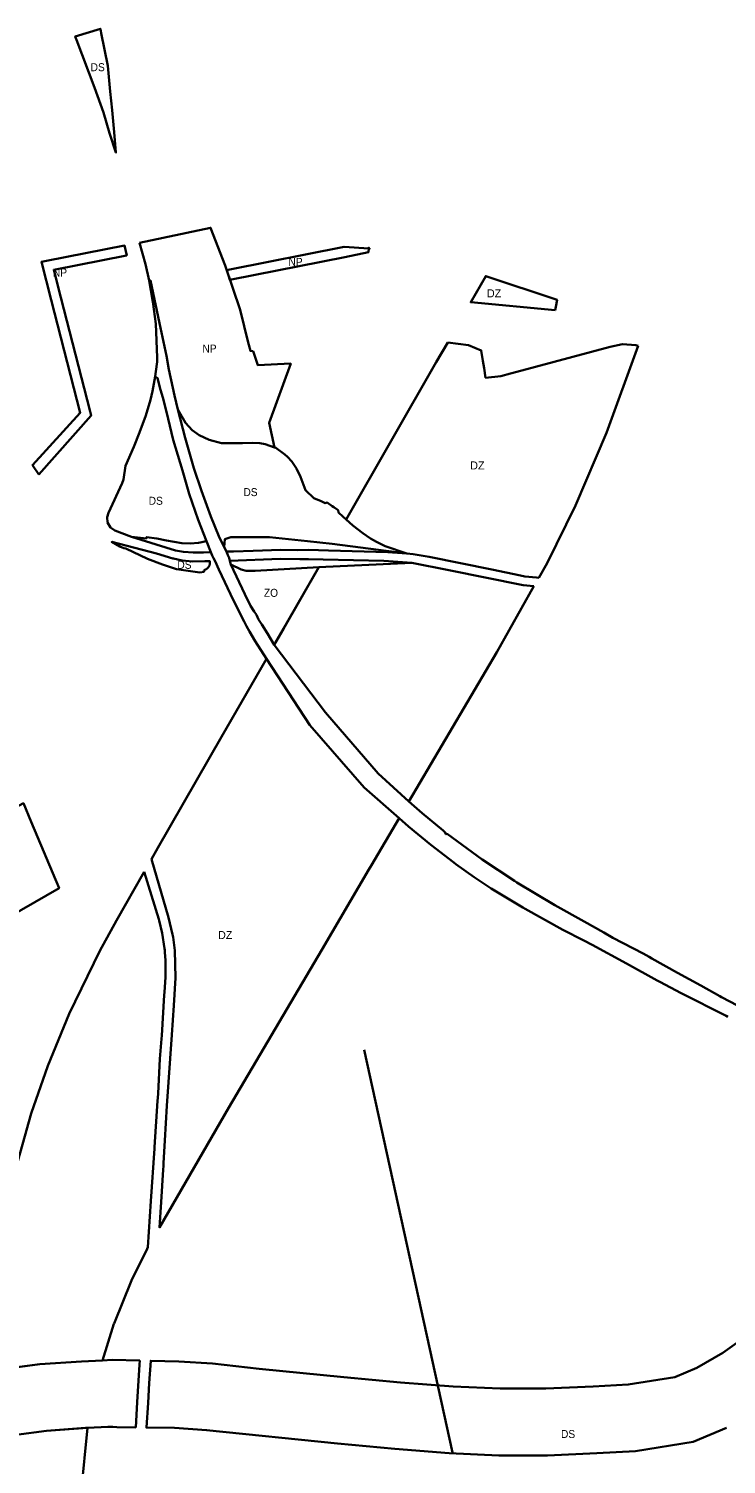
# Model space of a CAD drawing. Extents: x -650276 to -642489, y -1074311 to -1066658.
# Drawn here: x -647975 to -646929, y -1069108 to -1066956 of the extents above; entities that cross this region are included whole.
import ezdxf

# ---------------------------------------------------------------- set-up
doc = ezdxf.new("R2010")
doc.units = 0
doc.header["$LTSCALE"] = 4.8
doc.header["$PDMODE"] = 32
doc.header["$PDSIZE"] = 2.4
for name, color, linetype, lineweight in [('24', 7, 'Continuous', 35), ('25', 7, 'Continuous', 35), ('42', 7, 'Continuous', 35), ('48', 7, 'Continuous', 35), ('54', 7, 'Continuous', 35)]:
    doc.layers.add(name, color=color, linetype=linetype, lineweight=lineweight)
doc.layers.add('62', color=7, linetype='Continuous')
doc.layers.add('63', color=7, linetype='Continuous')

msp = doc.modelspace()

# ---------------------------------------------------------------- linework, layer by layer
at = {"layer": '24'}
for points in [[(-647876.57, -1067043.5), (-647863.04, -1067081.36), (-647853.65, -1067111.91), (-647844.3, -1067141.25), (-647847.09, -1067110.58), (-647850.07, -1067077.71), (-647852.63, -1067049.52), (-647856.11, -1067011.21), (-647866.14, -1066961.98), (-647867.46, -1066955.52), (-647905.28, -1066967.07), (-647903.5, -1066972.05)], [(-647754.88, -1067737.59), (-647743.12, -1067739.93), (-647728.29, -1067740.64), (-647713.15, -1067741), (-647702.21, -1067740.43), (-647708.71, -1067723.99), (-647720.45, -1067726.49), (-647732.71, -1067727.02), (-647745.41, -1067726.6), (-647768.53, -1067722.82), (-647783.13, -1067719.68), (-647798.17, -1067717.58), (-647798.5, -1067719.67), (-647821.02, -1067717.33)], [(-647596.91, -1067736.61), (-647572.33, -1067737.03), (-647555.58, -1067736.71), (-647525.685, -1067737.542), (-647436.72, -1067740.02), (-647408.2, -1067742.37), (-647520.145, -1067727.879), (-647557, -1067724), (-647614, -1067718), (-647643, -1067718), (-647672, -1067718), (-647680.804, -1067720.745), (-647681.91, -1067732.74), (-647678.66, -1067739.38), (-647678.66, -1067739.38), (-647667.76, -1067739.01), (-647638.75, -1067738.03)], [(-647540.208, -1067762.876), (-647400.63, -1067756.19), (-647442.6, -1067753.13), (-647533.597, -1067751.344), (-647555.67, -1067750.91), (-647568.36, -1067750.7), (-647597.83, -1067750.21), (-647673.47, -1067753.48), (-647672.05, -1067758.98), (-647672.05, -1067758.98), (-647656.469, -1067766.309), (-647649.22, -1067768.38), (-647635.758, -1067768.38)], [(-647540.208, -1067762.876), (-647400.63, -1067756.19), (-647442.6, -1067753.13), (-647533.597, -1067751.344), (-647555.67, -1067750.91), (-647568.36, -1067750.7), (-647597.83, -1067750.21), (-647673.47, -1067753.48), (-647672.05, -1067758.98), (-647672.05, -1067758.98), (-647656.469, -1067766.309), (-647649.22, -1067768.38), (-647635.758, -1067768.38)]]:
    msp.add_lwpolyline(points, close=True, dxfattribs=at)
for points in [[(-647606.818, -1067879.061), (-647617.25, -1067861.95), (-647625.37, -1067848.86), (-647630.3, -1067841.02), (-647633.69, -1067834.31), (-647637.21, -1067829.29), (-647642.29, -1067820.76), (-647650.8, -1067803.28), (-647672.05, -1067758.98), (-647673.47, -1067753.48), (-647673.47, -1067753.48), (-647674.67, -1067748.73), (-647676.47, -1067744.5), (-647678.66, -1067739.38), (-647681.91, -1067732.74), (-647690.09, -1067716.05), (-647702.04, -1067686.86), (-647715.92, -1067648.12), (-647727.37, -1067614.33), (-647740.49, -1067568.67), (-647751.41, -1067526.58), (-647756.55, -1067505.32), (-647759.16, -1067494.01), (-647764.89, -1067466.64), (-647768.5, -1067446.04), (-647778.78, -1067397.1), (-647792.52, -1067332.74), (-647794.54, -1067333.14), (-647788.77, -1067365.03), (-647784.55, -1067398.01), (-647782.39, -1067448.34), (-647782.5, -1067455.11), (-647784.36, -1067469.6), (-647785.64, -1067477.02), (-647781.85, -1067479.19), (-647777.55, -1067496.95), (-647773.96, -1067508.48), (-647768.5, -1067529.75), (-647758.25, -1067571.79), (-647744.61, -1067617.96), (-647734.63, -1067652.57), (-647721.05, -1067691.73), (-647708.71, -1067723.99), (-647702.21, -1067740.43), (-647699.89, -1067745.24), (-647697.85, -1067749.46), (-647695.71, -1067753.9), (-647690.19, -1067766.37), (-647668.13, -1067812.76), (-647651.94, -1067844.36), (-647648.33, -1067851.17), (-647643.83, -1067859.13), (-647635.77, -1067873.43), (-647618.773, -1067899.914)], [(-647708.71, -1067723.99), (-647721.05, -1067691.73), (-647734.63, -1067652.57), (-647744.61, -1067617.96), (-647758.25, -1067571.79), (-647768.5, -1067529.75), (-647773.96, -1067508.48), (-647777.55, -1067496.95), (-647781.85, -1067479.19), (-647785.64, -1067477.02), (-647789.39, -1067498.84), (-647792.54, -1067511.85), (-647799.39, -1067535.48)], [(-647799.39, -1067535.48), (-647808.71, -1067561.03), (-647817.59, -1067582.4)], [(-647654.743, -1067576.996), (-647685.968, -1067576.68), (-647704.458, -1067572.034), (-647719.661, -1067564.884), (-647729.802, -1067557.462), (-647740.124, -1067546.265), (-647751.41, -1067526.58)], [(-647751.41, -1067526.58), (-647740.49, -1067568.67), (-647727.37, -1067614.33), (-647715.92, -1067648.12), (-647702.04, -1067686.86)], [(-647817.59, -1067582.4), (-647829.97, -1067610.62), (-647832.8, -1067631.53), (-647835.06, -1067637.01), (-647855.24, -1067681.26), (-647857.51, -1067687.74), (-647856.9, -1067695.97)], [(-647606.559, -1067583.309), (-647620.586, -1067578.478), (-647628.441, -1067576.759), (-647640.087, -1067576.306), (-647654.743, -1067576.996)], [(-647547.663, -1067659.519), (-647560.187, -1067647.458), (-647567.744, -1067627.24), (-647573.605, -1067614.951), (-647580.539, -1067604.432), (-647586.864, -1067597.411), (-647591.227, -1067593.613), (-647604.415, -1067584.047), (-647606.559, -1067583.309)], [(-647499.095, -1067691.163), (-647503.97, -1067686.73), (-647510.6, -1067680.86), (-647511.24, -1067677.53), (-647517.74, -1067672.85), (-647520.13, -1067671.13), (-647527.76, -1067665.65), (-647530.82, -1067666.65), (-647536.83, -1067663.64), (-647547.663, -1067659.519)], [(-647702.04, -1067686.86), (-647690.09, -1067716.05), (-647681.91, -1067732.74)], [(-647462.45, -1067719.84), (-647474.13, -1067711.81), (-647489.3, -1067700.07), (-647499.095, -1067691.163)], [(-647856.9, -1067695.97), (-647852.3, -1067703.36), (-647845.74, -1067707.59), (-647821.02, -1067717.33)], [(-647783.54, -1067742.11), (-647850.45, -1067724.77), (-647838.18, -1067731.62), (-647832.56, -1067734.22), (-647829.49, -1067734.58), (-647796.87, -1067750.25), (-647774.54, -1067758.68), (-647753.53, -1067765.58), (-647718.54, -1067770.6), (-647712.01, -1067769.63), (-647712.26, -1067767.28)], [(-647821.02, -1067717.33), (-647798.5, -1067719.67), (-647798.17, -1067717.58), (-647783.13, -1067719.68), (-647768.53, -1067722.82), (-647745.41, -1067726.6), (-647732.71, -1067727.02), (-647720.45, -1067726.49), (-647708.71, -1067723.99)], [(-647681.91, -1067732.74), (-647680.804, -1067720.745), (-647672, -1067718), (-647643, -1067718), (-647614, -1067718)], [(-647614, -1067718), (-647557, -1067724), (-647520.145, -1067727.879), (-647408.2, -1067742.37), (-647440.81, -1067731.38), (-647453.87, -1067724.97), (-647462.45, -1067719.84)], [(-647712.26, -1067767.28), (-647711.773, -1067767.135), (-647711.286, -1067766.968), (-647710.799, -1067766.777), (-647710.315, -1067766.562), (-647709.834, -1067766.324), (-647709.359, -1067766.062), (-647708.892, -1067765.776), (-647708.433, -1067765.466), (-647707.985, -1067765.133), (-647707.55, -1067764.777), (-647707.128, -1067764.398), (-647706.723, -1067763.999), (-647706.335, -1067763.579), (-647705.966, -1067763.14), (-647705.617, -1067762.683), (-647705.29, -1067762.21), (-647704.985, -1067761.721), (-647704.704, -1067761.22), (-647704.447, -1067760.707), (-647704.216, -1067760.184), (-647704.01, -1067759.653), (-647703.83, -1067759.117), (-647703.675, -1067758.576), (-647703.547, -1067758.033), (-647703.445, -1067757.489), (-647703.368, -1067756.946), (-647703.315, -1067756.406), (-647703.287, -1067755.87), (-647703.282, -1067755.341), (-647703.3, -1067754.818), (-647703.34, -1067754.304), (-647703.4, -1067753.8), (-647711.09, -1067753.71), (-647728.98, -1067754.07), (-647734.69, -1067753.66), (-647744.74, -1067752.93), (-647757.74, -1067749.96), (-647759.13, -1067749.54), (-647783.54, -1067742.11)], [(-647405.026, -1068113.904), (-647451.024, -1068071.886), (-647530.038, -1067980.839), (-647606.818, -1067879.061)], [(-647618.773, -1067899.914), (-647553.628, -1067999.427), (-647472.338, -1068093.096), (-647419.713, -1068138.871)], [(-646864.48, -1068444.64), (-646936.47, -1068407.23), (-646938.95, -1068405.8), (-646967.64, -1068390), (-647002.71, -1068371.09), (-647040.77, -1068349.4), (-647044.93, -1068347.08), (-647053.75, -1068342.11), (-647099.2, -1068318.27), (-647112.813, -1068310.564), (-647142.41, -1068293.81), (-647186.26, -1068269.45), (-647243.39, -1068235.26), (-647246.8, -1068233.08), (-647295.47, -1068201.09), (-647347.74, -1068162.54), (-647349.59, -1068163.24), (-647350.6, -1068160.26), (-647353.81, -1068157.67), (-647385.13, -1068131.51), (-647405.026, -1068113.904)], [(-647419.713, -1068138.871), (-647405.71, -1068151.74), (-647372.38, -1068179.01), (-647337.74, -1068205.67), (-647334.62, -1068208.02), (-647307.39, -1068227.44), (-647281.64, -1068244.34), (-647234.11, -1068273.04), (-647230.83, -1068274.93), (-647174.56, -1068306.35), (-647142.788, -1068322.462), (-647130.29, -1068328.8), (-647079.16, -1068357.01), (-647032.91, -1068382.51), (-647029.23, -1068384.46), (-646997.06, -1068401.37), (-646929.56, -1068435.42), (-646927.06, -1068436.66)], [(-646894.206, -1068911.595), (-646934.465, -1068940.759), (-646973.61, -1068963.135), (-647006.63, -1068977.08), (-647076.422, -1068988.18), (-647128.674, -1068991.167), (-647199.672, -1068994.255), (-647268.348, -1068994.255), (-647338.816, -1068991.19), (-647417.895, -1068984.986), (-647502.412, -1068977.157), (-647629.424, -1068964.608), (-647699.561, -1068956.635), (-647749.978, -1068953.416), (-647792.01, -1068952.442), (-647794.21, -1068986.12), (-647796.13, -1069015.57), (-647798.631, -1069052.508), (-647756.441, -1069053.207), (-647708.401, -1069056.275), (-647511.94, -1069076.703), (-647426.417, -1069084.624), (-647344.902, -1069091.02), (-647270.522, -1069094.255), (-647197.498, -1069094.255), (-647123.648, -1069091.043), (-647065.688, -1069087.73), (-646978.92, -1069073.93), (-646929.186, -1069052.925)], [(-647864.531, -1068951.823), (-647895.901, -1068953.392), (-647958.168, -1068957.73), (-648038.596, -1068968.281), (-648038.759, -1068968.54)], [(-647808.28, -1068952.066), (-647850.043, -1068951.098), (-647864.531, -1068951.823)], [(-647814.401, -1069052.246), (-647812.34, -1069014.54), (-647808.67, -1068958.06), (-647808.28, -1068952.066)], [(-648040.705, -1069069.547), (-648039.666, -1069069.279), (-647948.18, -1069057.276), (-647886.615, -1069053.052), (-647856.541, -1069051.548), (-647848.615, -1069051.679), (-647842.888, -1069051.774), (-647814.401, -1069052.246)]]:
    msp.add_lwpolyline(points, dxfattribs=at)
at = {"layer": '25'}
msp.add_line((-648038.596, -1068968.281), (-647958.168, -1068957.73), dxfattribs=at)
msp.add_lwpolyline([(-647185.93, -1067377.38), (-647184.97, -1067372.22), (-647183.09, -1067362.16), (-647289.924, -1067326.309), (-647312.383, -1067365.484)], close=True, dxfattribs=at)
for points in [[(-647346.944, -1067425.768), (-647364.024, -1067455.561), (-647499.095, -1067691.163), (-647489.3, -1067700.07)], [(-647243.39, -1067469.81), (-647252.99, -1067472.35), (-647267.49, -1067476.23), (-647290.23, -1067478.89), (-647292.51, -1067464.56), (-647294.31, -1067453.26), (-647296.75, -1067437.91), (-647315.89, -1067429.71), (-647346.944, -1067425.768)], [(-647061.252, -1067430.908), (-647063.45, -1067430.19), (-647064.87, -1067429.73), (-647084.77, -1067428.64), (-647103.55, -1067432.54), (-647243.39, -1067469.81)], [(-647210.537, -1067778.594), (-647198.088, -1067756.5), (-647155.592, -1067670.17), (-647108.971, -1067561.55), (-647061.252, -1067430.908)], [(-647489.3, -1067700.07), (-647474.13, -1067711.81), (-647462.45, -1067719.84), (-647453.87, -1067724.97), (-647440.81, -1067731.38), (-647408.2, -1067742.37), (-647398.74, -1067743.15)], [(-647398.74, -1067743.15), (-647374.55, -1067747.34), (-647280.78, -1067766.44)], [(-647400.63, -1067756.19), (-647540.208, -1067762.876), (-647593.267, -1067855.425), (-647606.818, -1067879.061)], [(-647217.611, -1067791.149), (-647233.83, -1067789.69), (-647345.11, -1067767.28), (-647400.63, -1067756.19)], [(-647280.78, -1067766.44), (-647237.91, -1067775.18), (-647231.17, -1067776.55), (-647213.92, -1067778.26), (-647210.537, -1067778.594)], [(-647405.026, -1068113.904), (-647273.297, -1067889.981), (-647217.611, -1067791.149)], [(-647606.818, -1067879.061), (-647530.038, -1067980.839), (-647451.024, -1068071.886), (-647405.026, -1068113.904)], [(-647464.94, -1068215.752), (-647461.188, -1068209.373), (-647419.713, -1068138.871), (-647472.338, -1068093.096), (-647553.628, -1067999.427), (-647618.773, -1067899.914), (-647685.819, -1068016.861)], [(-647685.819, -1068016.861), (-647781.346, -1068183.485), (-647791.055, -1068200.507)], [(-647791.055, -1068200.507), (-647765.22, -1068287.94), (-647759.412, -1068313.436)], [(-647801.797, -1068219.34), (-647843.6, -1068292.629), (-647868.214, -1068337.803), (-647914.339, -1068432.512), (-647946.187, -1068510.254), (-647971.074, -1068581.98), (-647997.27, -1068674.747), (-648011.775, -1068739.718), (-648023.914, -1068809.332), (-648030.73, -1068861.213), (-648038.596, -1068968.281)], [(-647771.413, -1068334.626), (-647774.94, -1068311.47), (-647779.55, -1068292.23), (-647780.07, -1068290.53), (-647801.797, -1068219.34)], [(-647768.02, -1068570.36), (-647770.94, -1068622.47), (-647772.85, -1068656.41), (-647773.08, -1068660.57), (-647773.4, -1068665.71), (-647776.5, -1068714.8), (-647778.95, -1068752.433), (-647675.054, -1068572.919), (-647535.844, -1068336.279), (-647464.94, -1068215.752)], [(-647759.412, -1068313.436), (-647758.45, -1068317.66), (-647756.09, -1068337.61), (-647754.99, -1068378.21), (-647757.41, -1068419.98), (-647760.22, -1068463.96), (-647768.02, -1068570.36)], [(-647796.173, -1068782.191), (-647791.77, -1068713.23), (-647786.47, -1068634.37), (-647786.32, -1068632.19), (-647781.85, -1068562.97), (-647781.55, -1068558.38), (-647781.13, -1068551.88), (-647778.24, -1068499.95), (-647775.82, -1068469.74), (-647775.52, -1068464.97), (-647771.74, -1068404.5), (-647771.47, -1068400.07), (-647770.12, -1068377.5), (-647769.92, -1068352.1), (-647770.81, -1068340.29), (-647771.05, -1068337.01), (-647771.413, -1068334.626)], [(-647846.989, -1068896.545), (-647820.883, -1068832.117), (-647797.632, -1068784.713), (-647796.173, -1068782.191)], [(-647958.168, -1068957.73), (-647895.901, -1068953.392), (-647864.531, -1068951.823), (-647847.197, -1068897.199), (-647847.034, -1068896.687), (-647846.989, -1068896.545)], [(-647948.18, -1069057.276), (-648039.666, -1069069.279), (-648040.705, -1069069.548), (-648036.291, -1069139.458)], [(-647886.615, -1069053.052), (-647889.927, -1069053.218), (-647948.18, -1069057.276)], [(-647893.553, -1069279.017), (-647896.67, -1069213.573), (-647896.362, -1069149.171), (-647886.615, -1069053.052)]]:
    msp.add_lwpolyline(points, dxfattribs=at)
at = {"layer": '42'}
msp.add_lwpolyline([(-647606.818, -1067879.061), (-647540.208, -1067762.876), (-647635.758, -1067768.38), (-647649.22, -1067768.38), (-647656.469, -1067766.309), (-647672.05, -1067758.98), (-647650.8, -1067803.28), (-647642.29, -1067820.76), (-647637.21, -1067829.29), (-647633.69, -1067834.31), (-647630.3, -1067841.02), (-647625.37, -1067848.86), (-647617.25, -1067861.95)], close=True, dxfattribs=at)
at = {"layer": '48'}
for points in [[(-647638.68, -1067439.06), (-647642.686, -1067438.46), (-647645.78, -1067425.81), (-647658.13, -1067376.99), (-647680.64, -1067310.37), (-647702.42, -1067253.98), (-647809.02, -1067276.271)], [(-647882.66, -1067529.231), (-647926.759, -1067358.379), (-647937.355, -1067316.774), (-647828.376, -1067295.406), (-647828.104, -1067295.352), (-647831.28, -1067280.69), (-647948.488, -1067303.671)], [(-647809.02, -1067276.271), (-647799.76, -1067308.3), (-647794.54, -1067333.14)], [(-647948.488, -1067303.671), (-647955.805, -1067305.106), (-647941.289, -1067362.104)], [(-647465.203, -1067285.115), (-647501.968, -1067282.642), (-647673.685, -1067316.666), (-647678.21, -1067317.562), (-647673.367, -1067331.895), (-647670.77, -1067331.38), (-647501.099, -1067297.762)], [(-647501.099, -1067297.762), (-647465.699, -1067290.747), (-647465.203, -1067285.115)], [(-647794.54, -1067333.14), (-647792.52, -1067332.74), (-647778.78, -1067397.1), (-647768.5, -1067446.04), (-647764.89, -1067466.64), (-647759.16, -1067494.01)], [(-647941.289, -1067362.104), (-647897.637, -1067531.223), (-647969.29, -1067609.79), (-647959.832, -1067623.65)], [(-647751.41, -1067526.58), (-647740.124, -1067546.265), (-647729.802, -1067557.462), (-647719.661, -1067564.884), (-647704.458, -1067572.034), (-647685.968, -1067576.68), (-647654.743, -1067576.996), (-647640.087, -1067576.306), (-647628.441, -1067576.759), (-647620.586, -1067578.478), (-647606.559, -1067583.309), (-647614.75, -1067546.53), (-647582.2, -1067457.65), (-647631.59, -1067459.72), (-647638.68, -1067439.06)], [(-647759.16, -1067494.01), (-647756.55, -1067505.32), (-647751.41, -1067526.58)], [(-647959.832, -1067623.65), (-647881.085, -1067535.333), (-647882.66, -1067529.231)]]:
    msp.add_lwpolyline(points, dxfattribs=at)
msp.add_lwpolyline([(-648101.42, -1068344.28), (-648079.33, -1068330.03), (-647929.45, -1068244.16), (-647971.35, -1068144.48), (-647982.969, -1068116.575), (-648165.28, -1068214.465)], close=True, dxfattribs=at)
msp.add_point((-647465.203, -1067285.115), dxfattribs=at)
at = {"layer": '54'}
msp.add_line((-647472.11, -1068486.2), (-647340, -1069090), dxfattribs=at)

# ---------------------------------------------------------------- texts
at = {"layer": '62', "width": 0.95}
for s, p in [('NP', (-647585.583, -1067311.041)), ('NP', (-647938.583, -1067327.041)), ('NP', (-647714.583, -1067441.041)), ('DS', (-647653.118, -1067656.225)), ('DS', (-647795.118, -1067669.225)), ('DS', (-647752.118, -1067765.225)), ('ZO', (-647622.423, -1067807.188)), ('DS', (-647177.118, -1069068.225))]:
    msp.add_text(s, height=12, dxfattribs=at).set_placement(p)
at = {"layer": '62'}
for p in [(-647288.118, -1067358.225), (-647313.118, -1067616.225), (-647691.118, -1068320.225)]:
    msp.add_text('DZ', height=12, dxfattribs=at).set_placement(p)
at = {"layer": '63', "width": 0.95}
msp.add_text('DS', height=12, dxfattribs=at).set_placement((-647882.118, -1067019.225))

doc.saveas('drawing.dxf')
